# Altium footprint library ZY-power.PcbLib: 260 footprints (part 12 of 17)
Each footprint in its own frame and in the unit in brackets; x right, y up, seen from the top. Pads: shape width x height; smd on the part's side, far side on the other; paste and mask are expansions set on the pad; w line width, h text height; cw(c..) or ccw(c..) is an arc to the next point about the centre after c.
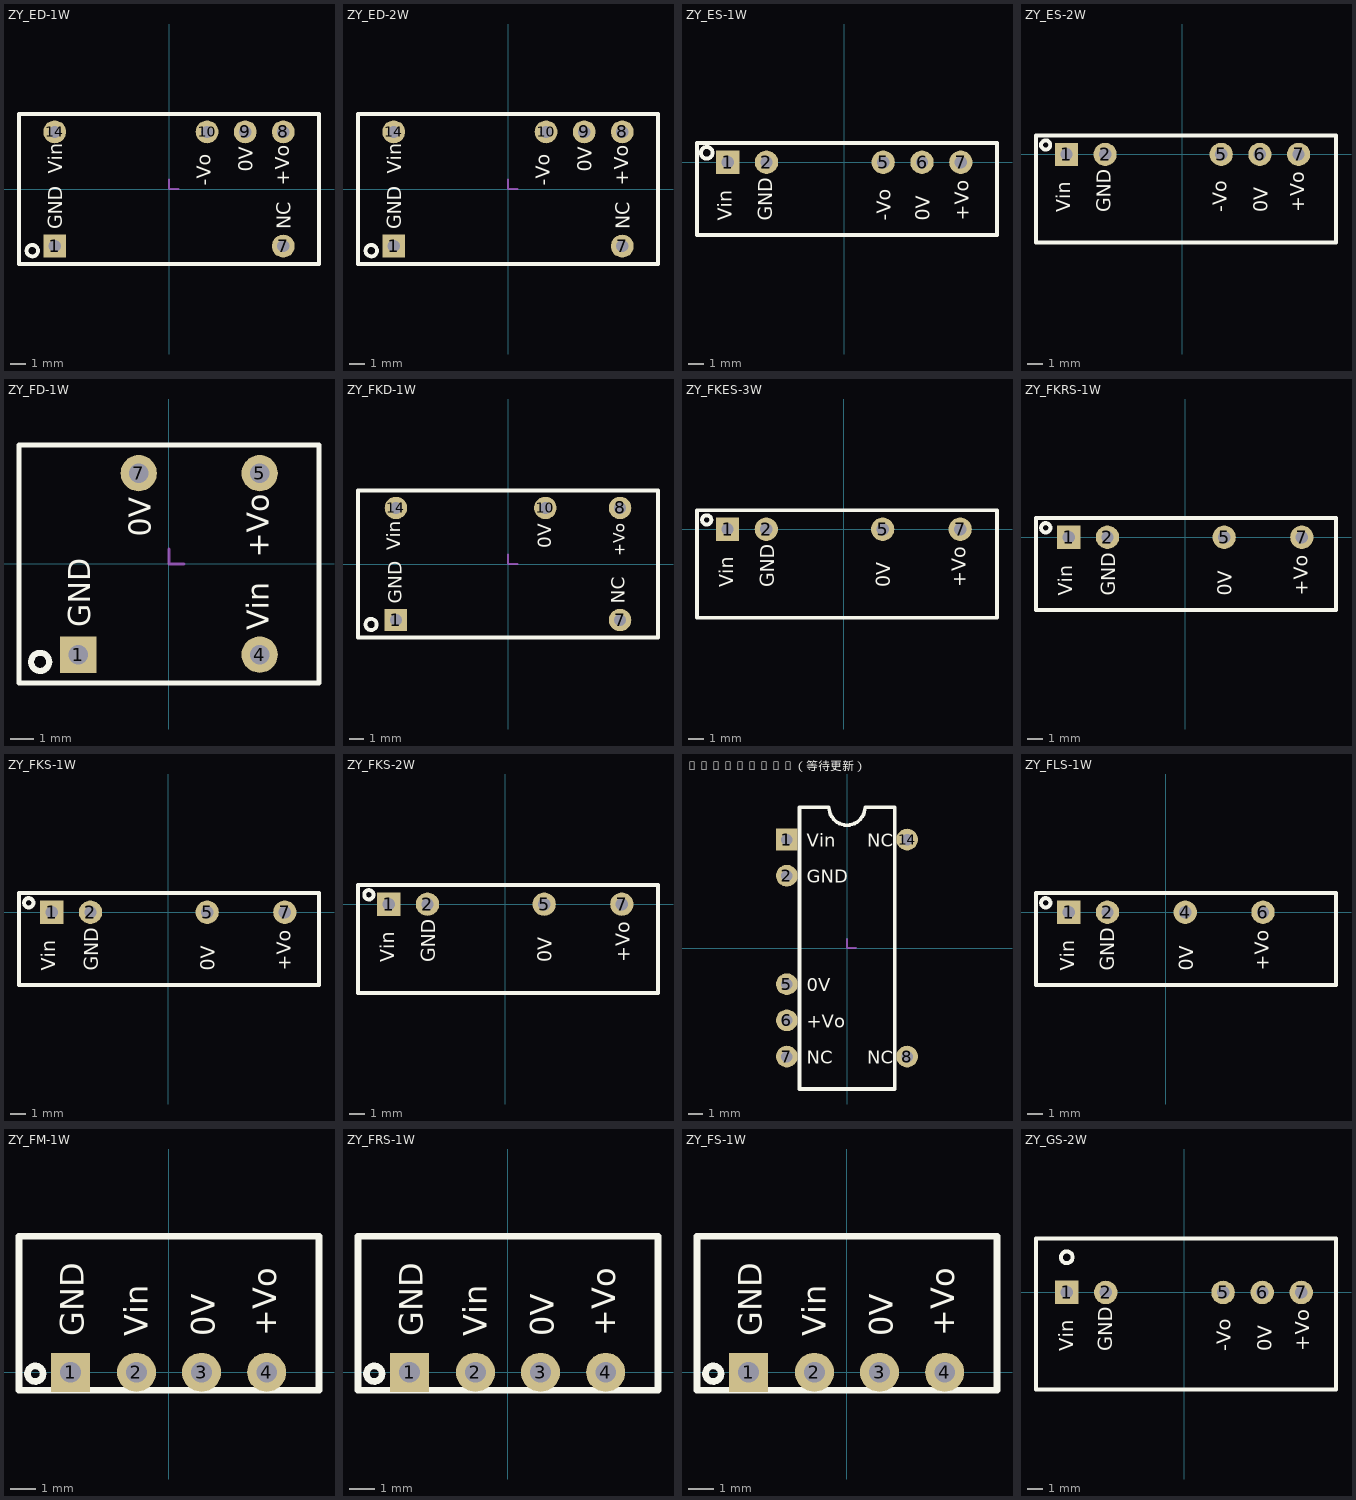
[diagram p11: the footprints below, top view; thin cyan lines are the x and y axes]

## ZY_ED-1W [mil] "定压输入隔离非稳压正、负输出"
height 275.59
pads (6):
  rect 60x60 hole 32: 1(-300,-150)
  round 60 hole 32: 7(300,-150) 8(300,150) 9(200,150) 10(100,150) 14(-300,150)
Top Overlay:
  circle w10: c-358.7,-161.85 r15
  lines w10: -393.7,-196.85 -354.72,-196.85 393.7,-196.85 393.7,196.85 -393.7,196.85 -393.7,-150 -393.7,-196.85
  text "GND" at -280,-105 h36
  text "NC" at 320,-105 h36
  text "Vin" at -280,40 h36
  text "-Vo" at 110,8.29 h36
  text "0V" at 220,44.63 h36
  text "+Vo" at 315,8.29 h36
Mechanical 15:
  lines w5: 0,25 0,0 25,0

## ZY_ED-2W [mil]
height 314.96
pads (6):
  rect 60x60 hole 32: 1(-300,-150)
  round 60 hole 32: 7(300,-150) 8(300,150) 9(200,150) 10(100,150) 14(-300,150)
Top Overlay:
  circle w10: c-358.7,-161.85 r15
  lines w10: -393.7,-196.85 -393.7,-150 -393.7,196.85 393.7,196.85 393.7,-196.85 -354.72,-196.85 -393.7,-196.85
  text "+Vo" at 315,8.29 h36
  text "0V" at 220,44.63 h36
  text "-Vo" at 110,8.29 h36
  text "Vin" at -280,40 h36
  text "NC" at 320,-105 h36
  text "GND" at -280,-105 h36
Mechanical 15:
  lines w5: 0,25 0,0 25,0

## ZY_ES-1W [mil] "定压输入隔离非稳压正、负输出"
height 393.7
pads (5):
  rect 60x60 hole 32: 1(-300,0)
  round 60 hole 32: 2(-200,0) 5(100,0) 6(200,0) 7(300,0)
Top Overlay:
  circle w10: c-353.74,24.21 r15
  lines w10: -378.74,-187.01 -378.74,49.21 392.91,49.21 392.91,-187.01 -378.74,-187.01
  text "+Vo" at 320,-150 h36
  text "0V" at 220,-150 h36
  text "-Vo" at 120,-150 h36
  text "GND" at -185,-150 h36
  text "Vin" at -290,-150 h36

## ZY_ES-2W [mil] "定压输入隔离非稳压双输出"
height 393.7
pads (5):
  rect 60x60 hole 32: 1(-300,0)
  round 60 hole 32: 2(-200,0) 5(100,0) 6(200,0) 7(300,0)
Top Overlay:
  circle w10: c-353.74,24.21 r12
  lines w10: -378.74,-228.35 396.85,-228.35 396.85,49.21 -378.74,49.21 -378.74,-228.35
  text "Vin" at -290,-150 h36
  text "GND" at -185,-150 h36
  text "-Vo" at 115,-150 h36
  text "0V" at 220,-150 h36
  text "+Vo" at 315,-150 h36

## ZY_FD-1W [mil] "定压输入隔离非稳压单输出"
height 303.15
pads (4):
  rect 60x60 hole 32: 1(-150,-150)
  round 60 hole 32: 4(150,-150) 5(150,150) 7(-50,150)
Top Overlay:
  circle w10: c-213,-162 r15
  lines w8: -248,-197 248.06,-197 248.06,196.7 -248,196.7 -248,-197
  text "0V" at -30,45 h36
  text "+Vo" at 165,10 h36
  text "Vin" at 165,-110 h36
  text "GND" at -130,-105 h36
Mechanical 15:
  lines w5: 0,25 0,0 25,0

## ZY_FKD-1W [mil]
height 314.96
pads (5):
  rect 60x60 hole 32: 1(-300,-150)
  round 60 hole 32: 7(300,-150) 8(300,150) 10(100,150) 14(-300,150)
Top Overlay:
  circle w10: c-366.57,-161.85 r15
  lines w10: -401.57,-196.85 401.57,-196.85 401.57,196.85 -401.57,196.85 -401.57,-196.85
  text "+Vo" at 312,21.26 h30
  text "0V" at 116,41.63 h36
  text "Vin" at -288,37 h36
  text "NC" at 312,-106 h36
  text "GND" at -284,-106 h36
Mechanical 15:
  lines w5: 0,25 0,0 25,0

## ZY_FKES-3W [mil]
pads (4):
  rect 60x60 hole 32: 1(-300,0)
  round 60 hole 32: 2(-200,0) 5(100,0) 7(300,0)
Top Overlay:
  circle w10: c-353.74,24.21 r12
  lines w10: 394.88,-228.23 394.88,49.21 -378.74,49.21 -378.74,-228.35 395,-228.35
  text "Vin" at -285,-150 h36
  text "GND" at -180,-150 h36
  text "0V" at 120,-150 h36
  text "+Vo" at 315,-150 h36

## ZY_FKRS-1W [mil]
height 393.7
pads (4):
  rect 60x60 hole 32: 1(-300,0)
  round 60 hole 32: 2(-200,0) 5(100,0) 7(300,0)
Top Overlay:
  circle w10: c-358.86,24.21 r12
  lines w10: -383.86,-187.01 -383.86,49.21 387.8,49.21 387.8,-187.01 -383.86,-187.01
  text "+Vo" at 315,-150 h36
  text "0V" at 120,-150 h36
  text "GND" at -180,-150 h36
  text "Vin" at -290,-150 h36

## ZY_FKS-1W [mil]
height 393.7
pads (4):
  rect 60x60 hole 32: 1(-300,0)
  round 60 hole 32: 2(-200,0) 5(100,0) 7(300,0)
Top Overlay:
  circle w10: c-358.86,24.21 r12
  lines w10: -383.86,-187.01 -383.86,49.21 387.8,49.21 387.8,-187.01 -383.86,-187.01
  text "+Vo" at 315,-150 h36
  text "0V" at 120,-150 h36
  text "GND" at -180,-150 h36
  text "Vin" at -290,-150 h36

## ZY_FKS-2W [mil] "定压输入隔离非稳压单输出"
height 393.7
pads (4):
  rect 60x60 hole 32: 1(-300,0)
  round 60 hole 32: 2(-200,0) 5(100,0) 7(300,0)
Top Overlay:
  circle w10: c-350.79,24.21 r12
  lines w10: -378.74,-228.35 -378.74,49.21 392.91,49.21 392.91,-228.35 -378.74,-228.35
  text "+Vo" at 320,-150 h36
  text "0V" at 120,-150 h36
  text "GND" at -180,-150 h36
  text "Vin" at -285,-150 h36

## ZY_FLD-1W（等待更新） [mil] "定压输入隔离非稳压单输出"
height 216.54
pads (7):
  rect 60x60 hole 32: 1(-166.34,300)
  round 60 hole 32: 2(-166.34,200) 5(-166.34,-100) 6(-166.34,-200) 7(-166.34,-300) 8(166.34,-300) 14(166.34,300)
Top Overlay:
  lines w10: -131.34,-389.76 131.66,-389.76 131.66,389.76 50,389.76 cw(c0,389.76) 0,339.76 cw(c0,389.76) -50,389.76 -131.34,389.76 -131.34,-389.76
  text "Vin" at -111.34,280 h36
  text "GND" at -111.34,180 h36
  text "+Vo" at -111.34,-220 h36
  text "0V" at -111.34,-120 h36
  text "NC" at -111.34,-320 h36
  text "NC" at 56.34,-320 h36
  text "NC" at 56.34,280 h36
Mechanical 15:
  lines w5: 0,25 0,0 25,0

## ZY_FLS-1W [mil]
height 393.7
pads (4):
  rect 60x60 hole 32: 1(-250,0)
  round 60 hole 32: 2(-150,0) 4(50,0) 6(250,0)
Top Overlay:
  circle w10: c-308.86,24.21 r12
  lines w10: -333.86,-187.01 437.8,-187.01 437.8,49.21 -333.86,49.21 -333.86,-187.01
  text "Vin" at -235,-150 h36
  text "GND" at -133,-150 h36
  text "0V" at 70,-150 h36
  text "+Vo" at 265,-150 h36

## ZY_FM-1W [mil]
height 393.7
pads (4):
  rect 60x60 hole 32: 1(-150.5,0)
  round 60 hole 32: 2(-49.5,0) 3(50.5,0) 4(150.5,0)
Top Overlay:
  circle w10: c-204.81,-2.2 r12
  lines w10: -229.81,-27.2 230.81,-27.2 230.81,209.02 -229.81,209.02 -229.81,-27.2
  text "GND" at -130.5,55 h36
  text "Vin" at -32.5,55 h36
  text "0V" at 70.5,55 h36
  text "+Vo" at 165.5,55 h36

## ZY_FRS-1W [mil]
height 393.7
pads (4):
  rect 60x60 hole 32: 1(-150.5,0)
  round 60 hole 32: 2(-49.5,0) 3(50.5,0) 4(150.5,0)
Top Overlay:
  circle w10: c-204.81,-2.2 r12
  lines w10: -229.81,-27.2 230.81,-27.2 230.81,209.02 -229.81,209.02 -229.81,-27.2
  text "GND" at -130.5,55 h36
  text "Vin" at -32.5,55 h36
  text "0V" at 70.5,55 h36
  text "+Vo" at 165.5,55 h36

## ZY_FS-1W [mil] "定压输入隔离非稳压单输出"
height 393.7
pads (4):
  rect 60x60 hole 32: 1(-150.5,0)
  round 60 hole 32: 2(-49.5,0) 3(50.5,0) 4(150.5,0)
Top Overlay:
  circle w10: c-204.81,-2.2 r12
  lines w10: -229.81,-27.2 -229.81,209.02 230.81,209.02 230.81,-27.2 -229.81,-27.2
  text "+Vo" at 165.5,55 h36
  text "0V" at 70.5,55 h36
  text "Vin" at -32.5,55 h36
  text "GND" at -130.5,55 h36

## ZY_GS-2W [mil]
pads (5):
  rect 60x60 hole 32 unplated: 1(-300,0)
  round 60 hole 32 unplated: 2(-200,0) 5(100,0) 6(200,0) 7(300,0)
Top Overlay:
  circle w10: c-300,90 r15
  lines w10: -378.74,-248.03 388.98,-248.03 388.98,137.8 -378.74,137.8 -378.74,-248.03
  text "Vin" at -283.74,-150 h36
  text "GND" at -183.74,-150 h36
  text "0V" at 225,-150 h36
  text "-Vo" at 120,-150 h36
  text "+Vo" at 320,-150 h36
